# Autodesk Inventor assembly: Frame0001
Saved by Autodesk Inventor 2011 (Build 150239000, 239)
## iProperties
Created: 2020-12
Part Number: Frame0001
Document SubType Name: Assembly
Designer: PC
_FrameDoc: Frame Assembly
_Version: 15.0.0
Author: PC
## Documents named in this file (8)
- C:\Users\PC\Documents\Inventor\workshop-crane-powered-by-drill\2_soporte-articulado\Frame\Frame0001.iam
- C:\Users\PC\Documents\Inventor\workshop-crane-powered-by-drill\2_soporte-articulado\Frame\Skeleton0001.ipt
- C:\Users\PC\Documents\Inventor\workshop-crane-powered-by-drill\2_soporte-articulado\Frame\DIN 60 x 60 x 4 00000001.ipt
- DIN 60 x 60 x 4 00000001.ipt
- C:\Users\PC\Documents\Inventor\workshop-crane-powered-by-drill\2_soporte-articulado\Frame\DIN 45 x 8 00000002.ipt
- DIN 45 x 8 00000002.ipt
- C:\Users\PC\Documents\Inventor\workshop-crane-powered-by-drill\2_soporte-articulado\Frame\DIN 45 x 8 00000003.ipt
- DIN 45 x 8 00000003.ipt
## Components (4 placed, 4 different names)
1. Frame Reference Model
2. DIN 60 x 60 x 4 00000001:1
3. DIN 45 x 8 00000002:1
4. DIN 45 x 8 00000003:1
